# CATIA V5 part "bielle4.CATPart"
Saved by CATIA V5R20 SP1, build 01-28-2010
Part number: bielle4
Bounding box of the stored display mesh (mm): x -88 to 10, y 235 to 265, z -235 to 45
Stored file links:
  C:\Users\Fabien-port\Desktop\test\bielle4.CATPart
  C:\Users\Fabien-port\Desktop\test\mecanisme_a_coulisseau.CATProduct
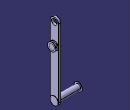
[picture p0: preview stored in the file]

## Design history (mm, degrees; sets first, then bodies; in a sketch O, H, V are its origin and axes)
External parameters (linked from other documents)
  External.largeur_bielle = 15 mm
  External.epaisseur_bielle = 8 mm
  External.rayon_cylindre_bielle = 10 mm
  External.cote_coulisseau = 30 mm
Set1
  Plane1 "Plan_pivot_E": linked copy from another document
  Point1 "PointE": linked copy from another document
  Point2 "PointD": linked copy from another document
  Point3 "PointB": linked copy from another document
Body1 (main body)
  Sketch1 on Plane1, origin (0, 0, 0), H (0, 1, 0), V (0, 0, 1)
    construction line L1 (250, 30) -> (250, -220)
    point P1 (250, 30)
    point P2 (250, -220)
    line L2 (265, 30) -> (265, -220)
    line L3 (235, -220) -> (235, 30)
    arc A1 centre (250, -220) radius 15 from (265, -220) to (235, -220) cw
    arc A2 centre (250, 30) radius 15 from (235, 30) to (265, 30) cw
    reference projected point E1 (250, 30) from Point1
    reference projected point E2 (250, -220) from Point2
    distance L1 L2 = 15 {= External.largeur_bielle}
    distance P1 E1 = 0
    distance P2 E2 = 0
    tangency: A1 L2, A2 L2, A1 L3, A2 L3
  Pad1: profile Sketch1, direction (-1, 0, 0), length 8 {= External.epaisseur_bielle}
  Sketch2 on Plane1, origin (0, 260, 70), H (0, 1, 0), V (0, 0, 1)
    point P1 (-10, -40)
    reference projected point E1 (-10, -40) from Point1
    coincidence: E1 P1
  Hole1: placed by Sketch2, at (0, 250, 30) direction (-1, 0, 0), diameter 20 {= External.rayon_cylindre_bielle *2}, depth 8 {= External.epaisseur_bielle}
  Sketch3 on start face of Pad1, origin (0, 0, 0), H (0, 1, 0), V (0, 0, 1)
    circle A1 centre (250, -45) radius 15
    point P1 (250, -45)
    reference projected point E1 (250, -45) from Point3
    radius A1 = 15 {= External.cote_coulisseau /2}
    distance P1 E1 = 0
  Pad2: profile Sketch3, direction (1, 0, 0), length 1
  Sketch4 on end face of Pad2, origin (1, 0, 0), H (0, 1, 0), V (0, 0, 1)
    circle A1 centre (250, -45) radius 10
    point P1 (250, -45)
    reference projected point E1 (250, -45) from Point3
    radius A1 = 10 {= External.rayon_cylindre_bielle}
    distance P1 E1 = 0
  Pad3: profile Sketch4, direction (1, 0, 0), length 8 {= External.epaisseur_bielle}
  Sketch5 on end face of Pad3, origin (9, 0, 0), H (0, 1, 0), V (0, 0, 1)
    circle A1 centre (250, -45) radius 15
    point P1 (250, -45)
    reference projected point E1 (250, -45) from Point3
    distance P1 E1 = 0
    radius A1 = 15 {= External.cote_coulisseau /2}
  Pad4: profile Sketch5, direction (1, 0, 0), length 1
  Sketch6 on end face of Pad1, origin (-8, 0, 0), H (0, -1, 0), V (0, 0, 1)
    circle A1 centre (-250, -45) radius 15
    point P1 (-250, -45)
    reference projected point E1 (-250, -45) from Point3
    distance P1 E1 = 0
    radius A1 = 15 {= External.cote_coulisseau /2}
  Pad5: profile Sketch6, direction (-1, 0, 0), length 1
  Sketch7 on start face of Pad1, origin (0, 0, 0), H (0, 1, 0), V (0, 0, 1)
    circle A1 centre (250, -220) radius 15
    point P1 (250, -220)
    reference projected point E1 (250, -220) from Point2
    radius A1 = 15 {= External.cote_coulisseau /2}
    distance P1 E1 = 0
  Pad6: profile Sketch7, direction (1, 0, 0), length 1
  Sketch8 on end face of Pad1, origin (-8, 0, 0), H (0, -1, 0), V (0, 0, 1)
    circle A1 centre (-250, -220) radius 15
    point P1 (-250, -220)
    reference projected point E1 (-250, -220) from Point2
    distance P1 E1 = 0
    radius A1 = 15 {= External.cote_coulisseau /2}
  Pad7: profile Sketch8, direction (-1, 0, 0), length 1
  Sketch9 on end face of Pad7, origin (-9, 0, 0), H (0, -1, 0), V (0, 0, 1)
    circle A1 centre (-250, -220) radius 10
    point P1 (-250, -220)
    reference projected point E1 (-250, -220) from Point2
    radius A1 = 10 {= External.rayon_cylindre_bielle}
    distance P1 E1 = 0
  Pad8: profile Sketch9, direction (-1, 0, 0), length 78 {= External.epaisseur_bielle *6+External.cote_coulisseau}
  Sketch10 on end face of Pad8, origin (-87, 0, 0), H (0, -1, 0), V (0, 0, 1)
    circle A1 centre (-250, -220) radius 15
    point P1 (-250, -220)
    reference projected point E1 (-250, -220) from Point2
    radius A1 = 15 {= External.cote_coulisseau /2}
    distance P1 E1 = 0
  Pad9: profile Sketch10, direction (-1, 0, 0), length 1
